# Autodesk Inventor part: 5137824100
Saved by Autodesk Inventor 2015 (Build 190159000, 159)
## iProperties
Created: 2020-07
Part Number: 5137824100
Checked By: TraceParts S.A.
Material: Generic
Catalog Web Link: www.traceparts.com
Document SubType Name: Modeling
Designer: TraceParts
Density: 1 g/cm^3
Appearance: Default
Company: TraceParts S.A.
Author: TraceParts
REFERENCE: 5137824100
DESIGN: CVAT/4-6000/450 N D PTC 0,75KW (230/400V) 50HZ - 5137824100
SUPPLIER: Soler & Palau
TraceParts.PartNumber: 10-14122018-105188
TraceParts.PartTitle: CVAT-N
TraceParts.InstanceId: 10-14122018-105188JGSO3BFL8KC94NIQ5TG87JA1
TraceParts.PartStatus: Published
TraceParts.PartVersion: 1.0.4
TRACEPARTS: TRACEPARTS
TraceParts.PartLanguage: en
TraceParts.ClassPath: SOLER_PALAU:10-14122018-105188
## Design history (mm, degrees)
feature "5137824100"
body "Solid1"
